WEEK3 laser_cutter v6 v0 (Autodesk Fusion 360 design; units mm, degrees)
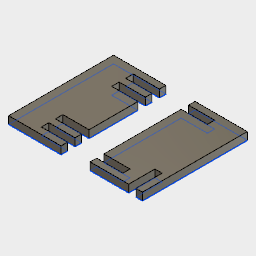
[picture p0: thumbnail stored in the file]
parameter "Parameter1" = 2
parameter "Parameter2" = 5
parameter "Function" = 15 (= "2 * ( Parameter1 * 2 ) + ( Parameter1 + Parameter2 )")
parameter "kerf" = 0.09
parameter "male" = 10.18 (= "d + 2 * kerf")
parameter "female" = 9.82 (= "d - 2 * kerf")
parameter "height" = 80
parameter "material_thickness" = 5.6
parameter "length" = 40
parameter "lunghezza_incastro" = 20
parameter "distanza_incastrilunghi" = 5
sketch "Sketch1" plane through (0, 0, 0) normal (0, 1, 0) x axis (1, 0, 0)
  line L1 (91.0645, 100.0161) -> (51.0645, 100.0161)
  line L2 (51.0645, 20.0161) -> (91.0645, 20.0161)
  line L3 (51.0645, 100.0161) -> (51.0645, 20.0161)
  line L4 (71.0645, 25.0161) -> (91.0645, 25.0161)
  line L5 (71.0645, 30.7061) -> (71.0645, 25.0161)
  line L6 (91.0645, 30.7061) -> (71.0645, 30.7061)
  line L7 (91.0645, 20.0161) -> (91.0645, 25.0161)
  line L8 (71.0645, 35.7061) -> (91.0645, 35.7061)
  line L9 (71.0645, 41.3961) -> (71.0645, 35.7061)
  line L10 (91.0645, 41.3961) -> (71.0645, 41.3961)
  line L11 (91.0645, 30.7061) -> (91.0645, 35.7061)
  line L12 (71.0645, 95.0161) -> (91.0645, 95.0161)
  line L13 (71.0645, 89.3261) -> (71.0645, 95.0161)
  line L14 (91.0645, 89.3261) -> (71.0645, 89.3261)
  line L15 (71.0645, 84.3261) -> (91.0645, 84.3261)
  line L16 (71.0645, 78.6361) -> (71.0645, 84.3261)
  line L17 (91.0645, 78.6361) -> (71.0645, 78.6361)
  line L18 (91.0645, 95.0161) -> (91.0645, 100.0161)
  line L19 (91.0645, 84.3261) -> (91.0645, 89.3261)
  line L20 (91.0645, 41.3961) -> (91.0645, 78.6361)
  line L21 (152.6178, 100.5646) -> (112.6178, 100.5646)
  line L22 (152.6178, 20.5646) -> (152.6178, 100.5646)
  line L23 (132.6178, 95.5646) -> (112.6178, 95.5646)
  line L24 (132.6178, 90.0546) -> (132.6178, 95.5646)
  line L25 (112.6178, 90.0546) -> (132.6178, 90.0546)
  line L26 (112.6178, 100.5646) -> (112.6178, 95.5646)
  line L27 (132.6178, 25.5646) -> (112.6178, 25.5646)
  line L28 (132.6178, 31.0746) -> (132.6178, 25.5646)
  line L29 (112.6178, 31.0746) -> (132.6178, 31.0746)
  line L30 (112.6178, 25.5646) -> (112.6178, 20.5646)
  line L31 (112.6178, 90.0546) -> (112.6178, 31.0746)
  line L32 (142.1078, 40.5646) -> (142.1078, 20.5646)
  line L33 (147.6178, 40.5646) -> (142.1078, 40.5646)
  line L34 (147.6178, 20.5646) -> (147.6178, 40.5646)
  line L35 (147.6178, 20.5646) -> (152.6178, 20.5646)
  line L36 (112.6178, 20.5646) -> (142.1078, 20.5646)
  point P2 (51.0645, 100.0161)
  point P5 (51.0645, 20.0161)
  point P3 (91.0645, 100.0161)
  point P7 (71.0645, 25.0161)
  point P8 (71.0645, 30.7061)
  point P9 (91.0645, 30.7061)
  point P10 (91.0645, 35.7061)
  point P11 (71.0645, 35.7061)
  point P12 (71.0645, 41.3961)
  point P4 (91.0645, 20.0161)
  point P6 (91.0645, 25.0161)
  point P15 (71.0645, 95.0161)
  point P16 (71.0645, 89.3261)
  point P14 (91.0645, 95.0161)
  point P17 (91.0645, 89.3261)
  point P18 (91.0645, 84.3261)
  point P19 (71.0645, 84.3261)
  point P20 (71.0645, 78.6361)
  point P21 (91.0645, 78.6361)
  point P22 (112.6178, 100.5646)
  point P23 (152.6178, 100.5646)
  point P24 (152.6178, 20.5646)
  point P28 (132.6178, 90.0546)
  point P29 (112.6178, 90.0546)
  point P26 (112.6178, 95.5646)
  point P27 (132.6178, 95.5646)
  point P32 (132.6178, 31.0746)
  point P33 (112.6178, 31.0746)
  point P31 (132.6178, 25.5646)
  point P25 (112.6178, 20.5646)
  point P30 (112.6178, 25.5646)
  point P37 (147.6178, 20.5646)
  point P35 (142.1078, 40.5646)
  point P36 (147.6178, 40.5646)
  dimension "d33" distance P2 P5 = 80 (= "height")
  dimension "d34" distance P2 P3 = 40 (= "length")
  dimension "d35" distance P7 P8 = 5.69 (= "material_thickness + kerf")
  dimension "d36" distance P8 P9 = 20 (= "lunghezza_incastro")
  dimension "d38" distance P10 P11 = 20 (= "lunghezza_incastro")
  dimension "d39" distance P11 P12 = 5.69 (= "material_thickness + kerf")
  dimension "d40" distance P4 P6 = 5 (= "distanza_incastrilunghi")
  dimension "d41" distance P9 P10 = 5 (= "distanza_incastrilunghi")
  dimension "d43" distance P15 P16 = 5.69 (= "material_thickness + kerf")
  dimension "d44" distance P3 P14 = 5 (= "distanza_incastrilunghi")
  dimension "d45" distance P16 P17 = 20 (= "lunghezza_incastro")
  dimension "d46" distance P17 P18 = 5 (= "distanza_incastrilunghi")
  dimension "d47" distance P19 P20 = 5.69 (= "material_thickness + kerf")
  dimension "d48" distance P20 P21 = 20 (= "lunghezza_incastro")
  dimension "d49" distance P22 P23 = 40 (= "length")
  dimension "d50" distance P23 P24 = 80 (= "height")
  dimension "d51" distance P28 P29 = 20 (= "lunghezza_incastro")
  dimension "d52" distance P22 P26 = 5 (= "distanza_incastrilunghi")
  dimension "d53" distance P27 P28 = 5.51 (= "material_thickness - kerf")
  dimension "d54" distance P32 P33 = 20 (= "lunghezza_incastro")
  dimension "d55" distance P31 P32 = 5.51 (= "material_thickness - kerf")
  dimension "d56" distance P25 P30 = 5 (= "distanza_incastrilunghi")
  dimension "d57" distance P24 P37 = 5 (= "distanza_incastrilunghi")
  dimension "d58" distance P35 P36 = 5.51 (= "material_thickness - kerf")
  dimension "d59" distance P36 P37 = 20 (= "lunghezza_incastro")
extrude "Extrude1" new body sketch "Sketch1" profile of L1 L20 L2 L3 L4 L5 L6 L8 L9 L10 L12 L13 L14 L15 L16 L17 L21 L22 L36 L31 L23 L24 L25 L27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 along normal blind 5
extrude "Extrude2" add sketch "Sketch1" profile of L1 L20 L2 L3 L4 L5 L6 L8 L9 L10 L12 L13 L14 L15 L16 L17 L21 L22 L36 L31 L23 L24 L25 L27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 blind 5.85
